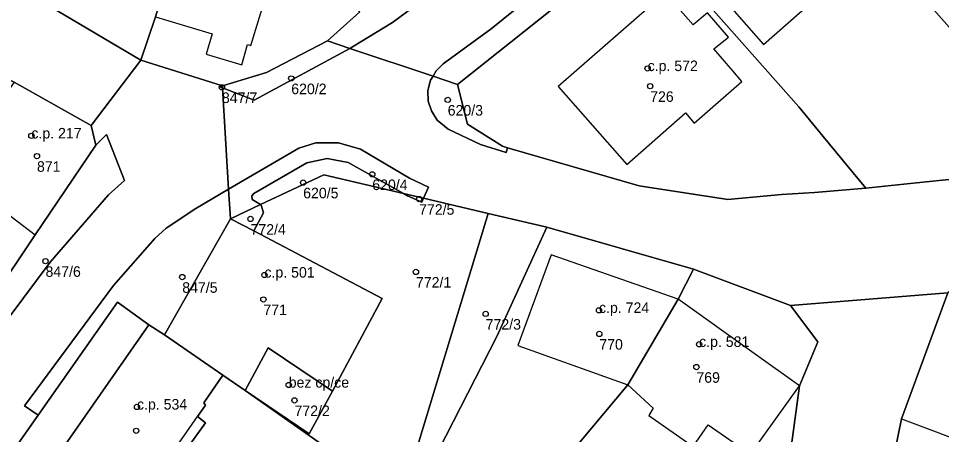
# Model space of a CAD drawing. Extents: x -878211 to -870363, y -1058464 to -1052522.
# Drawn here: x -874758 to -874670.5, y -1056517.4 to -1056478 of the extents above; entities that cross this region are included whole.
import ezdxf

# ---------------------------------------------------------------- set-up
doc = ezdxf.new("R2010")
doc.units = 0
for name, color, linetype in [('Vrstva 50', 7, 'Continuous'), ('Vrstva 51', 7, 'Continuous'), ('Vrstva 52', 7, 'Continuous')]:
    doc.layers.add(name, color=color, linetype=linetype)

msp = doc.modelspace()

# ---------------------------------------------------------------- linework, layer by layer
at = {"layer": 'Vrstva 50'}
for centre in [(-874698.4, -1056482.68994), (-874732.18, -1056483.63994), (-874698.16, -1056484.36994), (-874738.75, -1056484.47994), (-874717.35, -1056485.66994), (-874756.81, -1056489.07994), (-874756.28, -1056490.99994), (-874724.5, -1056492.72994), (-874731.05, -1056493.50994), (-874720.06, -1056495.06994), (-874736.04, -1056496.95994), (-874755.47, -1056500.95994), (-874742.51, -1056502.46994), (-874734.72, -1056502.26994), (-874720.36, -1056501.97994), (-874734.82, -1056504.58994), (-874713.75, -1056505.95994), (-874703.01, -1056505.61994), (-874702.98, -1056507.85994), (-874693.52, -1056508.83994), (-874693.78, -1056510.99994), (-874732.42, -1056512.69994), (-874731.87, -1056514.15994), (-874746.8, -1056514.77994), (-874746.88, -1056517.03994)]:
    msp.add_circle(centre, 0.25, dxfattribs=at)
at = {"layer": 'Vrstva 51'}
for points in [[(-874663.52, -1056438.4), (-874672.43, -1056441.48), (-874672.5, -1056441.7), (-874673.54, -1056443), (-874674.2, -1056443.48), (-874682.75, -1056447.86), (-874689.17, -1056451.94), (-874695.4, -1056456.68), (-874715.47, -1056473.07), (-874722.59, -1056478.34), (-874726.37, -1056480.65), (-874726.62, -1056480.79), (-874718.74, -1056483.43), (-874718.45, -1056482.93), (-874717.77, -1056482.26), (-874713.22, -1056478.92), (-874687.75, -1056458.39), (-874684.49, -1056456.15), (-874678.51, -1056452.48), (-874674.25, -1056450.17), (-874670.55, -1056448.41), (-874665.5, -1056446.52)], [(-874665.5, -1056446.52), (-874670.55, -1056448.41), (-874674.25, -1056450.17), (-874678.51, -1056452.48), (-874684.49, -1056456.15), (-874687.75, -1056458.39), (-874713.22, -1056478.92), (-874717.77, -1056482.26), (-874718.45, -1056482.93), (-874718.74, -1056483.43), (-874716.43, -1056484.2), (-874698.53, -1056469.97), (-874686.86, -1056459.52), (-874673.94, -1056451.62), (-874671.18, -1056450.63), (-874653.34, -1056444.21)], [(-874725.69, -1056477.31), (-874728.74, -1056480.08), (-874726.62, -1056480.79), (-874726.37, -1056480.65), (-874722.59, -1056478.34), (-874715.47, -1056473.07)], [(-874658.14, -1056492.03), (-874672.92, -1056493.55), (-874677.72, -1056494.05), (-874682.57, -1056494.44), (-874685.72, -1056494.63), (-874690.79, -1056495.11), (-874699.2, -1056493.82), (-874711.67, -1056490.22), (-874711.81, -1056490.67), (-874714.23, -1056489.9), (-874717.32, -1056488.46), (-874718.34, -1056487.59), (-874718.89, -1056486.72), (-874719.21, -1056485.79), (-874719.22, -1056484.77), (-874718.97, -1056483.81), (-874718.74, -1056483.43), (-874726.62, -1056480.79), (-874735.69, -1056485.69), (-874738.7, -1056484.54)], [(-874763.27, -1056525.64), (-874756.17, -1056515.56), (-874757.46, -1056514.66), (-874749.04, -1056503.26), (-874745.11, -1056498.8), (-874744.03, -1056497.83), (-874741.22, -1056495.96), (-874738.12, -1056494.14), (-874738.7, -1056484.54), (-874738.95, -1056484.44), (-874738.71, -1056484.33), (-874746.43, -1056481.89), (-874751.15, -1056488.09), (-874750.71, -1056489.97), (-874749.7, -1056488.95), (-874747.99, -1056493.3), (-874749.51, -1056494.67), (-874755.04, -1056501.07), (-874762.73, -1056511.37), (-874764.42, -1056510.19), (-874768.48, -1056516.12), (-874775.04, -1056525.67)], [(-874738.7, -1056484.54), (-874738.12, -1056494.14), (-874731.47, -1056490.24), (-874729.85, -1056489.73), (-874727.7, -1056489.73), (-874725.63, -1056490.35), (-874720.98, -1056493.08), (-874719.18, -1056493.93), (-874719.64, -1056494.99), (-874713.52, -1056496.43), (-874707.96, -1056497.73), (-874694.05, -1056501.72), (-874684.86, -1056505.16), (-874669.94, -1056503.95)], [(-874675.79, -1056523.03), (-874674.34, -1056515.92), (-874669.94, -1056503.95), (-874684.86, -1056505.16), (-874682.26, -1056508.62), (-874684.02, -1056512.77), (-874685.26, -1056522.1)]]:
    msp.add_lwpolyline(points, dxfattribs=at)
for points in [[(-874746.43, -1056481.89), (-874754.95, -1056476.89), (-874763.22, -1056475.22), (-874774.43, -1056469.49), (-874777.11, -1056468.31), (-874792.6, -1056460.75), (-874795.75, -1056458.63), (-874796.48, -1056457.88), (-874796.08, -1056457.01), (-874799.5, -1056454.73), (-874803.79, -1056451.88), (-874813.86, -1056445.18), (-874811.44, -1056456.7), (-874804.76, -1056460.13), (-874796.2, -1056464.61), (-874787.26, -1056469.19), (-874780.67, -1056472.7), (-874779.11, -1056473.48), (-874770.31, -1056477.96), (-874761.17, -1056482.65), (-874758.44, -1056484), (-874751.15, -1056488.09)], [(-874745.05, -1056477.8), (-874742.21, -1056468.41), (-874744.75, -1056467.68), (-874743.73, -1056464.03), (-874742.87, -1056460.95), (-874753.3, -1056456.92), (-874756.19, -1056464.33), (-874757.22, -1056464.04), (-874758.27, -1056463.52), (-874762.27, -1056472.9), (-874763.22, -1056475.22), (-874754.95, -1056476.89), (-874746.43, -1056481.89)], [(-874686.86, -1056459.52), (-874698.53, -1056469.97), (-874684.07, -1056486.33), (-874681.76, -1056489.14), (-874677.72, -1056494.05), (-874672.92, -1056493.55), (-874658.14, -1056492.03), (-874671.51, -1056476.89)], [(-874738.71, -1056484.33), (-874734.51, -1056483.09), (-874728.74, -1056480.08), (-874725.69, -1056477.31), (-874726.52, -1056476.31), (-874731.9, -1056471.1), (-874732.33, -1056468.29), (-874741.48, -1056464.85), (-874743.73, -1056464.03), (-874744.75, -1056467.68), (-874742.21, -1056468.41), (-874745.05, -1056477.8), (-874746.43, -1056481.89)], [(-874712.17, -1056490.07), (-874711.67, -1056490.22), (-874699.2, -1056493.82), (-874690.79, -1056495.11), (-874685.72, -1056494.63), (-874682.57, -1056494.44), (-874677.72, -1056494.05), (-874681.76, -1056489.14), (-874684.07, -1056486.33), (-874698.53, -1056469.97), (-874716.43, -1056484.2), (-874715.48, -1056487.98)], [(-874650.8, -1056475.84), (-874654.76, -1056475.57), (-874662.19, -1056475.65), (-874666.67, -1056477.08), (-874667.61, -1056473.41), (-874671.51, -1056476.89), (-874658.14, -1056492.03), (-874651.63, -1056491.41), (-874651.42, -1056490.62), (-874650.75, -1056483.21), (-874651.15, -1056483.19)], [(-874738.71, -1056484.33), (-874738.7, -1056484.54), (-874735.69, -1056485.69), (-874726.62, -1056480.79), (-874728.74, -1056480.08), (-874734.51, -1056483.09)], [(-874756.45, -1056498.46), (-874750.71, -1056489.97), (-874751.15, -1056488.09), (-874758.44, -1056484), (-874761.17, -1056482.65), (-874766.12, -1056491.04), (-874765.94, -1056494.47), (-874768.7, -1056498.27), (-874767.89, -1056498.83), (-874766.17, -1056500.02), (-874760.51, -1056504.47)], [(-874718.74, -1056483.43), (-874718.97, -1056483.81), (-874719.22, -1056484.77), (-874719.21, -1056485.79), (-874718.89, -1056486.72), (-874718.34, -1056487.59), (-874717.32, -1056488.46), (-874714.23, -1056489.9), (-874711.81, -1056490.67), (-874711.67, -1056490.22), (-874712.17, -1056490.07), (-874715.48, -1056487.98), (-874716.43, -1056484.2)], [(-874738.7, -1056484.54), (-874738.71, -1056484.33), (-874738.95, -1056484.44)], [(-874760.51, -1056504.47), (-874764.42, -1056510.19), (-874762.73, -1056511.37), (-874755.04, -1056501.07), (-874749.51, -1056494.67), (-874747.99, -1056493.3), (-874749.7, -1056488.95), (-874750.71, -1056489.97), (-874756.45, -1056498.46)], [(-874735.1, -1056495.6), (-874735.87, -1056495.13), (-874735.9, -1056494.78), (-874735.72, -1056494.53), (-874730.7, -1056491.63), (-874728.76, -1056491.23), (-874726.8, -1056491.6), (-874721.53, -1056494.55), (-874719.64, -1056494.99), (-874719.18, -1056493.93), (-874720.98, -1056493.08), (-874725.63, -1056490.35), (-874727.7, -1056489.73), (-874729.85, -1056489.73), (-874731.47, -1056490.24), (-874738.12, -1056494.14), (-874737.95, -1056496.94)], [(-874735.1, -1056495.6), (-874729.09, -1056492.77), (-874721.53, -1056494.55), (-874726.8, -1056491.6), (-874728.76, -1056491.23), (-874730.7, -1056491.63), (-874735.72, -1056494.53), (-874735.9, -1056494.78), (-874735.87, -1056495.13)], [(-874721.15, -1056494.76), (-874721.53, -1056494.55), (-874729.09, -1056492.77), (-874735.1, -1056495.6), (-874735.02, -1056495.65), (-874734.82, -1056496.37), (-874735.74, -1056498.1), (-874723.55, -1056504.49), (-874728.26, -1056513.3), (-874730.47, -1056517.32), (-874736.56, -1056513.22), (-874725.57, -1056520.93), (-874721.37, -1056522.37), (-874713.52, -1056496.43), (-874719.64, -1056494.99), (-874719.81, -1056495.38)], [(-874737.95, -1056496.94), (-874738.12, -1056494.14), (-874741.22, -1056495.96), (-874744.03, -1056497.83), (-874745.11, -1056498.8), (-874749.04, -1056503.26), (-874757.46, -1056514.66), (-874756.17, -1056515.56), (-874748.64, -1056504.86), (-874745.67, -1056507), (-874744.18, -1056507.93)], [(-874719.81, -1056495.38), (-874719.64, -1056494.99), (-874721.53, -1056494.55), (-874721.15, -1056494.76)], [(-874737.95, -1056496.94), (-874735.74, -1056498.1), (-874734.82, -1056496.37), (-874735.02, -1056495.65), (-874735.1, -1056495.6)], [(-874707.96, -1056497.73), (-874713.52, -1056496.43), (-874721.37, -1056522.37), (-874720.15, -1056522.79), (-874719.59, -1056521.58), (-874712.68, -1056508.1)], [(-874737.95, -1056496.94), (-874744.18, -1056507.93), (-874738.66, -1056511.77), (-874736.56, -1056513.22), (-874734.36, -1056509.18), (-874728.26, -1056513.3), (-874723.55, -1056504.49), (-874735.74, -1056498.1)], [(-874707.96, -1056497.73), (-874712.68, -1056508.1), (-874719.59, -1056521.58), (-874720.15, -1056522.79), (-874721.31, -1056525.34), (-874718.3, -1056526.65), (-874716.44, -1056527.64), (-874713.87, -1056529.89), (-874704.82, -1056518.11), (-874700.29, -1056512.7), (-874695.5, -1056504.57), (-874694.05, -1056501.72)], [(-874669.94, -1056503.95), (-874674.34, -1056515.92), (-874675.79, -1056523.03), (-874648.58, -1056527.34), (-874649.03, -1056518.95), (-874649.23, -1056515.1), (-874649.31, -1056513.05), (-874650.24, -1056500.68), (-874653.13, -1056500.77), (-874656.59, -1056501.1), (-874667.91, -1056502.32)], [(-874688.12, -1056530.7), (-874685.26, -1056522.1), (-874684.02, -1056512.77), (-874682.26, -1056508.62), (-874684.86, -1056505.16), (-874694.05, -1056501.72), (-874695.5, -1056504.57), (-874700.29, -1056512.7), (-874704.82, -1056518.11), (-874701.37, -1056521.07), (-874699.33, -1056522.89), (-874697.32, -1056524.25)], [(-874756.17, -1056515.56), (-874763.27, -1056525.64), (-874769.01, -1056533.49), (-874765.98, -1056535.78), (-874760.19, -1056527.76), (-874745.67, -1056507), (-874748.64, -1056504.86)], [(-874745.67, -1056507), (-874760.19, -1056527.76), (-874765.98, -1056535.78), (-874758.76, -1056541.24), (-874749.93, -1056529.65), (-874740.3, -1056516.3), (-874741.06, -1056515.69), (-874740.3, -1056514.6), (-874740.47, -1056514.4), (-874738.66, -1056511.77), (-874744.18, -1056507.93)], [(-874736.56, -1056513.22), (-874730.47, -1056517.32), (-874728.26, -1056513.3), (-874734.36, -1056509.18)], [(-874723.49, -1056537.85), (-874716.44, -1056527.64), (-874718.3, -1056526.65), (-874721.31, -1056525.34), (-874720.15, -1056522.79), (-874721.37, -1056522.37), (-874725.57, -1056520.93), (-874736.56, -1056513.22), (-874738.66, -1056511.77), (-874740.47, -1056514.4), (-874740.3, -1056514.6), (-874741.06, -1056515.69), (-874740.3, -1056516.3), (-874749.93, -1056529.65), (-874746.56, -1056532.21), (-874740.28, -1056523.43), (-874732.01, -1056529.37), (-874738.3, -1056538.14), (-874728.64, -1056545.02)]]:
    msp.add_lwpolyline(points, close=True, dxfattribs=at)
at = {"layer": 'Vrstva 52'}
for points in [[(-874693.85, -1056473.06), (-874687.43, -1056480.41), (-874678.31, -1056472.38), (-874684.73, -1056465.04)], [(-874745.05, -1056477.8), (-874739.68, -1056479.4), (-874740.25, -1056481.34), (-874736.87, -1056482.34), (-874736.32, -1056480.43), (-874736.01, -1056480.5), (-874733.17, -1056471.2), (-874742.21, -1056468.41)], [(-874706.88, -1056484.4), (-874700.38, -1056491.8), (-874694.82, -1056486.91), (-874693.98, -1056487.87), (-874689.47, -1056483.92), (-874690.32, -1056482.93), (-874692.13, -1056480.82), (-874690.75, -1056479.72), (-874692.72, -1056477.42), (-874694.07, -1056478.56), (-874696.75, -1056475.52)], [(-874764.37, -1056492.43), (-874756.45, -1056498.46), (-874750.71, -1056489.97), (-874751.15, -1056488.09), (-874758.44, -1056484)], [(-874723.55, -1056504.49), (-874735.74, -1056498.1), (-874737.95, -1056496.94), (-874744.18, -1056507.93), (-874738.66, -1056511.77), (-874736.56, -1056513.22), (-874734.36, -1056509.18), (-874728.26, -1056513.3)], [(-874710.7, -1056508.95), (-874700.29, -1056512.7), (-874695.5, -1056504.57), (-874707.54, -1056500.37)], [(-874669.94, -1056503.95), (-874674.34, -1056515.92), (-874666.85, -1056518.73), (-874664.16, -1056511.46), (-874663.48, -1056512.85), (-874657.83, -1056512.22), (-874658.21, -1056508.8), (-874655.77, -1056508.33), (-874656.59, -1056501.1), (-874667.91, -1056502.32)], [(-874700.29, -1056512.7), (-874697.87, -1056514.9), (-874698.3, -1056515.58), (-874694.1, -1056518.54), (-874692.67, -1056516.47), (-874688.64, -1056519.27), (-874684.02, -1056512.77), (-874688.3, -1056509.72), (-874695.5, -1056504.57)], [(-874741.06, -1056515.69), (-874740.3, -1056514.6), (-874740.47, -1056514.4), (-874738.66, -1056511.77), (-874744.18, -1056507.93), (-874745.67, -1056507), (-874760.19, -1056527.76), (-874754.81, -1056531.56), (-874747.89, -1056521.57), (-874746.05, -1056522.85)], [(-874734.36, -1056509.18), (-874736.56, -1056513.22), (-874730.47, -1056517.32), (-874728.26, -1056513.3)]]:
    msp.add_lwpolyline(points, close=True, dxfattribs=at)

# ---------------------------------------------------------------- texts
at = {"layer": 'Vrstva 50'}
for s, p in [('c.p. 572', (-874698.4, -1056482.94)), ('620/2', (-874732.18, -1056485.129)), ('847/7', (-874738.75, -1056485.969)), ('726', (-874698.16, -1056485.859)), ('620/3', (-874717.35, -1056487.159)), ('c.p. 217', (-874756.81, -1056489.33)), ('871', (-874756.28, -1056492.489)), ('620/4', (-874724.5, -1056494.219)), ('620/5', (-874731.05, -1056494.999)), ('772/5', (-874720.06, -1056496.559)), ('772/4', (-874736.04, -1056498.449)), ('847/6', (-874755.47, -1056502.449)), ('c.p. 501', (-874734.72, -1056502.52)), ('772/1', (-874720.36, -1056503.469)), ('847/5', (-874742.51, -1056503.959)), ('771', (-874734.82, -1056506.079)), ('c.p. 724', (-874703.01, -1056505.87)), ('772/3', (-874713.75, -1056507.449)), ('770', (-874702.98, -1056509.349)), ('c.p. 581', (-874693.52, -1056509.09)), ('bez cp/ce', (-874732.42, -1056512.95)), ('769', (-874693.78, -1056512.489)), ('c.p. 534', (-874746.8, -1056515.03)), ('772/2', (-874731.87, -1056515.649))]:
    msp.add_text(s, height=0.999996, dxfattribs=at).set_placement(p)

doc.saveas('drawing.dxf')
